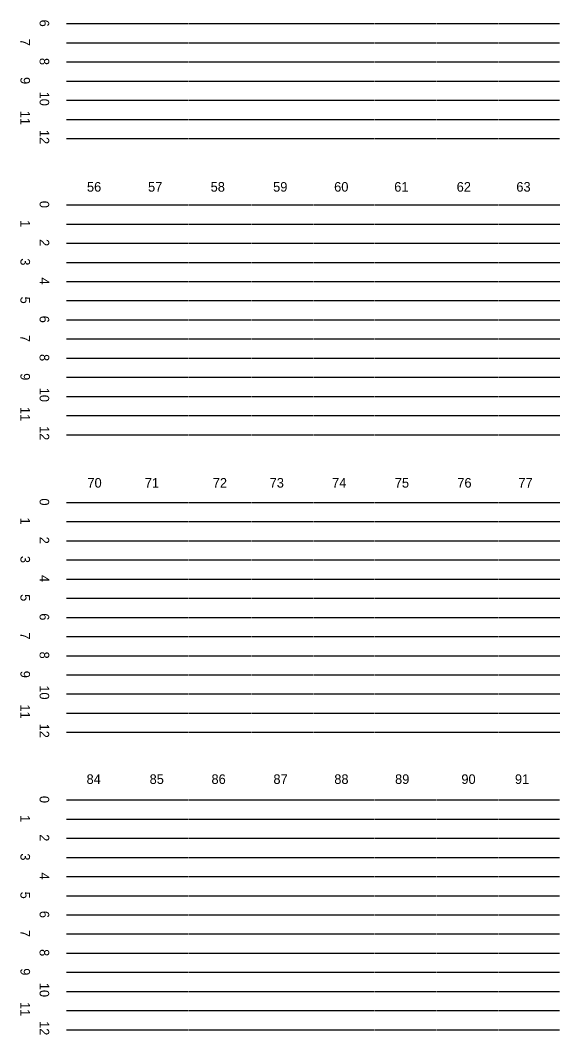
# Model space of a CAD drawing. Extents: x 11193 to 12507, y 10092 to 10555.
# Drawn here: x 11193.1 to 11315, y 10091.7 to 10321.2 of the extents above; entities that cross this region are included whole.
import ezdxf

# ---------------------------------------------------------------- set-up
doc = ezdxf.new("R2010")
doc.units = 0
doc.layers.add('Level 2', color=7, linetype='Continuous')

msp = doc.modelspace()

# ---------------------------------------------------------------- linework, layer by layer
at = {"layer": 'Level 2'}
for p, q in [((11203.54, 10320.47), (11217.46, 10320.47)), ((11217.56, 10320.47), (11231.14, 10320.47)), ((11231.24, 10320.47), (11245.22, 10320.47)), ((11245.32, 10320.47), (11259.3, 10320.47)), ((11259.41, 10320.47), (11273.18, 10320.47)), ((11273.29, 10320.47), (11287.06, 10320.47)), ((11287.17, 10320.47), (11301.14, 10320.47)), ((11301.25, 10320.47), (11315.03, 10320.47)), ((11203.54, 10316.14), (11217.46, 10316.14)), ((11217.56, 10316.14), (11231.14, 10316.14)), ((11231.24, 10316.14), (11245.22, 10316.14)), ((11245.32, 10316.14), (11259.3, 10316.14)), ((11259.41, 10316.14), (11273.18, 10316.14)), ((11273.29, 10316.14), (11287.06, 10316.14)), ((11287.17, 10316.14), (11301.14, 10316.14)), ((11301.25, 10316.14), (11315.03, 10316.14)), ((11203.54, 10311.81), (11217.46, 10311.81)), ((11217.56, 10311.81), (11231.14, 10311.81)), ((11231.24, 10311.81), (11245.22, 10311.81)), ((11245.32, 10311.81), (11259.3, 10311.81)), ((11259.41, 10311.81), (11273.18, 10311.81)), ((11273.29, 10311.81), (11287.06, 10311.81)), ((11287.17, 10311.81), (11301.14, 10311.81)), ((11301.25, 10311.81), (11315.03, 10311.81)), ((11203.54, 10307.48), (11217.46, 10307.48)), ((11217.56, 10307.48), (11231.14, 10307.48)), ((11231.24, 10307.48), (11245.22, 10307.48)), ((11245.32, 10307.48), (11259.3, 10307.48)), ((11259.41, 10307.48), (11273.18, 10307.48)), ((11273.29, 10307.48), (11287.06, 10307.48)), ((11287.17, 10307.48), (11301.14, 10307.48)), ((11301.25, 10307.48), (11315.03, 10307.48)), ((11203.54, 10303.14), (11217.46, 10303.14)), ((11217.56, 10303.14), (11231.14, 10303.14)), ((11231.24, 10303.14), (11245.22, 10303.14)), ((11245.32, 10303.14), (11259.3, 10303.14)), ((11259.41, 10303.14), (11273.18, 10303.14)), ((11273.29, 10303.14), (11287.06, 10303.14)), ((11287.17, 10303.14), (11301.14, 10303.14)), ((11301.25, 10303.14), (11315.03, 10303.14)), ((11203.54, 10298.81), (11217.46, 10298.81)), ((11217.56, 10298.81), (11231.14, 10298.81)), ((11231.24, 10298.81), (11245.22, 10298.81)), ((11245.32, 10298.81), (11259.3, 10298.81)), ((11259.41, 10298.81), (11273.18, 10298.81)), ((11273.29, 10298.81), (11287.06, 10298.81)), ((11287.17, 10298.81), (11301.14, 10298.81)), ((11301.25, 10298.81), (11315.03, 10298.81)), ((11203.54, 10294.48), (11217.46, 10294.48)), ((11217.56, 10294.48), (11231.14, 10294.48)), ((11231.24, 10294.48), (11245.22, 10294.48)), ((11245.32, 10294.48), (11259.3, 10294.48)), ((11259.41, 10294.48), (11273.18, 10294.48)), ((11273.29, 10294.48), (11287.06, 10294.48)), ((11287.17, 10294.48), (11301.14, 10294.48)), ((11301.25, 10294.48), (11315.03, 10294.48)), ((11203.54, 10279.46), (11217.47, 10279.46)), ((11217.59, 10279.46), (11231.15, 10279.46)), ((11231.26, 10279.46), (11245.23, 10279.46)), ((11245.35, 10279.46), (11259.31, 10279.46)), ((11259.43, 10279.46), (11273.2, 10279.46)), ((11273.31, 10279.46), (11287.08, 10279.46)), ((11287.18, 10279.46), (11301.16, 10279.46)), ((11301.26, 10279.46), (11315.04, 10279.46)), ((11203.54, 10275.13), (11217.47, 10275.13)), ((11217.59, 10275.13), (11231.15, 10275.13)), ((11231.26, 10275.13), (11245.23, 10275.13)), ((11245.35, 10275.13), (11259.31, 10275.13)), ((11259.43, 10275.13), (11273.2, 10275.13)), ((11273.31, 10275.13), (11287.08, 10275.13)), ((11287.18, 10275.13), (11301.16, 10275.13)), ((11301.26, 10275.13), (11315.04, 10275.13)), ((11203.54, 10270.79), (11217.47, 10270.79)), ((11217.59, 10270.79), (11231.15, 10270.79)), ((11231.26, 10270.79), (11245.23, 10270.79)), ((11245.35, 10270.79), (11259.31, 10270.79)), ((11259.43, 10270.79), (11273.2, 10270.79)), ((11273.31, 10270.79), (11287.08, 10270.79)), ((11287.18, 10270.79), (11301.16, 10270.79)), ((11301.26, 10270.79), (11315.04, 10270.79)), ((11203.54, 10266.46), (11217.47, 10266.46)), ((11217.59, 10266.46), (11231.15, 10266.46)), ((11231.26, 10266.46), (11245.23, 10266.46)), ((11245.35, 10266.46), (11259.31, 10266.46)), ((11259.43, 10266.46), (11273.2, 10266.46)), ((11273.31, 10266.46), (11287.08, 10266.46)), ((11287.18, 10266.46), (11301.16, 10266.46)), ((11301.26, 10266.46), (11315.04, 10266.46)), ((11203.54, 10262.13), (11217.47, 10262.13)), ((11217.59, 10262.13), (11231.15, 10262.13)), ((11231.26, 10262.13), (11245.23, 10262.13)), ((11245.35, 10262.13), (11259.31, 10262.13)), ((11259.43, 10262.13), (11273.2, 10262.13)), ((11273.31, 10262.13), (11287.08, 10262.13)), ((11287.18, 10262.13), (11301.16, 10262.13)), ((11301.26, 10262.13), (11315.04, 10262.13)), ((11203.54, 10257.8), (11217.47, 10257.8)), ((11217.59, 10257.8), (11231.15, 10257.8)), ((11231.26, 10257.8), (11245.23, 10257.8)), ((11245.35, 10257.8), (11259.31, 10257.8)), ((11259.43, 10257.8), (11273.2, 10257.8)), ((11273.31, 10257.8), (11287.08, 10257.8)), ((11287.18, 10257.8), (11301.16, 10257.8)), ((11301.26, 10257.8), (11315.04, 10257.8)), ((11203.54, 10253.47), (11217.47, 10253.47)), ((11217.59, 10253.47), (11231.15, 10253.47)), ((11231.26, 10253.47), (11245.23, 10253.47)), ((11245.35, 10253.47), (11259.31, 10253.47)), ((11259.43, 10253.47), (11273.2, 10253.47)), ((11273.31, 10253.47), (11287.08, 10253.47)), ((11287.18, 10253.47), (11301.16, 10253.47)), ((11301.26, 10253.47), (11315.04, 10253.47)), ((11203.54, 10249.13), (11217.47, 10249.13)), ((11217.59, 10249.13), (11231.15, 10249.13)), ((11231.26, 10249.13), (11245.23, 10249.13)), ((11245.35, 10249.13), (11259.31, 10249.13)), ((11259.43, 10249.13), (11273.2, 10249.13)), ((11273.31, 10249.13), (11287.08, 10249.13)), ((11287.18, 10249.13), (11301.16, 10249.13)), ((11301.26, 10249.13), (11315.04, 10249.13)), ((11203.54, 10244.8), (11217.47, 10244.8)), ((11217.59, 10244.8), (11231.15, 10244.8)), ((11231.26, 10244.8), (11245.23, 10244.8)), ((11245.35, 10244.8), (11259.31, 10244.8)), ((11259.43, 10244.8), (11273.2, 10244.8)), ((11273.31, 10244.8), (11287.08, 10244.8)), ((11287.18, 10244.8), (11301.16, 10244.8)), ((11301.26, 10244.8), (11315.04, 10244.8)), ((11203.54, 10240.47), (11217.47, 10240.47)), ((11217.59, 10240.47), (11231.15, 10240.47)), ((11231.26, 10240.47), (11245.23, 10240.47)), ((11245.35, 10240.47), (11259.31, 10240.47)), ((11259.43, 10240.47), (11273.2, 10240.47)), ((11273.31, 10240.47), (11287.08, 10240.47)), ((11287.18, 10240.47), (11301.16, 10240.47)), ((11301.26, 10240.47), (11315.04, 10240.47)), ((11203.54, 10236.14), (11217.47, 10236.14)), ((11217.59, 10236.14), (11231.15, 10236.14)), ((11231.26, 10236.14), (11245.23, 10236.14)), ((11245.35, 10236.14), (11259.31, 10236.14)), ((11259.43, 10236.14), (11273.2, 10236.14)), ((11273.31, 10236.14), (11287.08, 10236.14)), ((11287.18, 10236.14), (11301.16, 10236.14)), ((11301.26, 10236.14), (11315.04, 10236.14)), ((11203.54, 10231.81), (11217.47, 10231.81)), ((11217.59, 10231.81), (11231.15, 10231.81)), ((11231.26, 10231.81), (11245.23, 10231.81)), ((11245.35, 10231.81), (11259.31, 10231.81)), ((11259.43, 10231.81), (11273.2, 10231.81)), ((11273.31, 10231.81), (11287.08, 10231.81)), ((11287.18, 10231.81), (11301.16, 10231.81)), ((11301.26, 10231.81), (11315.04, 10231.81)), ((11203.54, 10227.47), (11217.47, 10227.47)), ((11217.59, 10227.47), (11231.15, 10227.47)), ((11231.26, 10227.47), (11245.23, 10227.47)), ((11245.35, 10227.47), (11259.31, 10227.47)), ((11259.43, 10227.47), (11273.2, 10227.47)), ((11273.31, 10227.47), (11287.08, 10227.47)), ((11287.18, 10227.47), (11301.16, 10227.47)), ((11301.26, 10227.47), (11315.04, 10227.47)), ((11203.54, 10212.14), (11217.47, 10212.14)), ((11217.59, 10212.14), (11231.15, 10212.14)), ((11231.26, 10212.14), (11245.23, 10212.14)), ((11245.35, 10212.14), (11259.31, 10212.14)), ((11259.43, 10212.14), (11273.2, 10212.14)), ((11273.31, 10212.14), (11287.08, 10212.14)), ((11287.18, 10212.14), (11301.16, 10212.14)), ((11301.26, 10212.14), (11315.04, 10212.14)), ((11203.54, 10207.81), (11217.47, 10207.81)), ((11217.59, 10207.81), (11231.15, 10207.81)), ((11231.26, 10207.81), (11245.23, 10207.81)), ((11245.35, 10207.81), (11259.31, 10207.81)), ((11259.43, 10207.81), (11273.2, 10207.81)), ((11273.31, 10207.81), (11287.08, 10207.81)), ((11287.18, 10207.81), (11301.16, 10207.81)), ((11301.26, 10207.81), (11315.04, 10207.81)), ((11203.54, 10203.48), (11217.47, 10203.48)), ((11217.59, 10203.48), (11231.15, 10203.48)), ((11231.26, 10203.48), (11245.23, 10203.48)), ((11245.35, 10203.48), (11259.31, 10203.48)), ((11259.43, 10203.48), (11273.2, 10203.48)), ((11273.31, 10203.48), (11287.08, 10203.48)), ((11287.18, 10203.48), (11301.16, 10203.48)), ((11301.26, 10203.48), (11315.04, 10203.48)), ((11203.54, 10199.14), (11217.47, 10199.14)), ((11217.59, 10199.14), (11231.15, 10199.14)), ((11231.26, 10199.14), (11245.23, 10199.14)), ((11245.35, 10199.14), (11259.31, 10199.14)), ((11259.43, 10199.14), (11273.2, 10199.14)), ((11273.31, 10199.14), (11287.08, 10199.14)), ((11287.18, 10199.14), (11301.16, 10199.14)), ((11301.26, 10199.14), (11315.04, 10199.14)), ((11203.54, 10194.81), (11217.47, 10194.81)), ((11217.59, 10194.81), (11231.15, 10194.81)), ((11231.26, 10194.81), (11245.23, 10194.81)), ((11245.35, 10194.81), (11259.31, 10194.81)), ((11259.43, 10194.81), (11273.2, 10194.81)), ((11273.31, 10194.81), (11287.08, 10194.81)), ((11287.18, 10194.81), (11301.16, 10194.81)), ((11301.26, 10194.81), (11315.04, 10194.81)), ((11203.54, 10190.48), (11217.47, 10190.48)), ((11217.59, 10190.48), (11231.15, 10190.48)), ((11231.26, 10190.48), (11245.23, 10190.48)), ((11245.35, 10190.48), (11259.31, 10190.48)), ((11259.43, 10190.48), (11273.2, 10190.48)), ((11273.31, 10190.48), (11287.08, 10190.48)), ((11287.18, 10190.48), (11301.16, 10190.48)), ((11301.26, 10190.48), (11315.04, 10190.48)), ((11203.54, 10186.15), (11217.47, 10186.15)), ((11217.59, 10186.15), (11231.15, 10186.15)), ((11231.26, 10186.15), (11245.23, 10186.15)), ((11245.35, 10186.15), (11259.31, 10186.15)), ((11259.43, 10186.15), (11273.2, 10186.15)), ((11273.31, 10186.15), (11287.08, 10186.15)), ((11287.18, 10186.15), (11301.16, 10186.15)), ((11301.26, 10186.15), (11315.04, 10186.15)), ((11203.54, 10181.82), (11217.47, 10181.82)), ((11217.59, 10181.82), (11231.15, 10181.82)), ((11231.26, 10181.82), (11245.23, 10181.82)), ((11245.35, 10181.82), (11259.31, 10181.82)), ((11259.43, 10181.82), (11273.2, 10181.82)), ((11273.31, 10181.82), (11287.08, 10181.82)), ((11287.18, 10181.82), (11301.16, 10181.82)), ((11301.26, 10181.82), (11315.04, 10181.82)), ((11203.54, 10177.48), (11217.47, 10177.48)), ((11217.59, 10177.48), (11231.15, 10177.48)), ((11231.26, 10177.48), (11245.23, 10177.48)), ((11245.35, 10177.48), (11259.31, 10177.48)), ((11259.43, 10177.48), (11273.2, 10177.48)), ((11273.31, 10177.48), (11287.08, 10177.48)), ((11287.18, 10177.48), (11301.16, 10177.48)), ((11301.26, 10177.48), (11315.04, 10177.48)), ((11203.54, 10173.15), (11217.47, 10173.15)), ((11217.59, 10173.15), (11231.15, 10173.15)), ((11231.26, 10173.15), (11245.23, 10173.15)), ((11245.35, 10173.15), (11259.31, 10173.15)), ((11259.43, 10173.15), (11273.2, 10173.15)), ((11273.31, 10173.15), (11287.08, 10173.15)), ((11287.18, 10173.15), (11301.16, 10173.15)), ((11301.26, 10173.15), (11315.04, 10173.15)), ((11203.54, 10168.82), (11217.47, 10168.82)), ((11217.59, 10168.82), (11231.15, 10168.82)), ((11231.26, 10168.82), (11245.23, 10168.82)), ((11245.35, 10168.82), (11259.31, 10168.82)), ((11259.43, 10168.82), (11273.2, 10168.82)), ((11273.31, 10168.82), (11287.08, 10168.82)), ((11287.18, 10168.82), (11301.16, 10168.82)), ((11301.26, 10168.82), (11315.04, 10168.82)), ((11203.54, 10164.49), (11217.47, 10164.49)), ((11217.59, 10164.49), (11231.15, 10164.49)), ((11231.26, 10164.49), (11245.23, 10164.49)), ((11245.35, 10164.49), (11259.31, 10164.49)), ((11259.43, 10164.49), (11273.2, 10164.49)), ((11273.31, 10164.49), (11287.08, 10164.49)), ((11287.18, 10164.49), (11301.16, 10164.49)), ((11301.26, 10164.49), (11315.04, 10164.49)), ((11203.54, 10160.16), (11217.47, 10160.16)), ((11217.59, 10160.16), (11231.15, 10160.16)), ((11231.26, 10160.16), (11245.23, 10160.16)), ((11245.35, 10160.16), (11259.31, 10160.16)), ((11259.43, 10160.16), (11273.2, 10160.16)), ((11273.31, 10160.16), (11287.08, 10160.16)), ((11287.18, 10160.16), (11301.16, 10160.16)), ((11301.26, 10160.16), (11315.04, 10160.16)), ((11203.54, 10144.83), (11217.46, 10144.83)), ((11217.56, 10144.83), (11231.14, 10144.83)), ((11231.24, 10144.83), (11245.22, 10144.83)), ((11245.32, 10144.83), (11259.3, 10144.83)), ((11259.41, 10144.83), (11273.18, 10144.83)), ((11273.29, 10144.83), (11287.06, 10144.83)), ((11287.17, 10144.83), (11301.14, 10144.83)), ((11301.25, 10144.83), (11315.03, 10144.83)), ((11203.54, 10140.5), (11217.46, 10140.5)), ((11217.56, 10140.5), (11231.14, 10140.5)), ((11231.24, 10140.5), (11245.22, 10140.5)), ((11245.32, 10140.5), (11259.3, 10140.5)), ((11259.41, 10140.5), (11273.18, 10140.5)), ((11273.29, 10140.5), (11287.06, 10140.5)), ((11287.17, 10140.5), (11301.14, 10140.5)), ((11301.25, 10140.5), (11315.03, 10140.5)), ((11203.54, 10136.17), (11217.46, 10136.17)), ((11217.56, 10136.17), (11231.14, 10136.17)), ((11231.24, 10136.17), (11245.22, 10136.17)), ((11245.32, 10136.17), (11259.3, 10136.17)), ((11259.41, 10136.17), (11273.18, 10136.17)), ((11273.29, 10136.17), (11287.06, 10136.17)), ((11287.17, 10136.17), (11301.14, 10136.17)), ((11301.25, 10136.17), (11315.03, 10136.17)), ((11203.54, 10131.84), (11217.46, 10131.84)), ((11217.56, 10131.84), (11231.14, 10131.84)), ((11231.24, 10131.84), (11245.22, 10131.84)), ((11245.32, 10131.84), (11259.3, 10131.84)), ((11259.41, 10131.84), (11273.18, 10131.84)), ((11273.29, 10131.84), (11287.06, 10131.84)), ((11287.17, 10131.84), (11301.14, 10131.84)), ((11301.25, 10131.84), (11315.03, 10131.84)), ((11203.54, 10127.51), (11217.46, 10127.51)), ((11217.56, 10127.51), (11231.14, 10127.51)), ((11231.24, 10127.51), (11245.22, 10127.51)), ((11245.32, 10127.51), (11259.3, 10127.51)), ((11259.41, 10127.51), (11273.18, 10127.51)), ((11273.29, 10127.51), (11287.06, 10127.51)), ((11287.17, 10127.51), (11301.14, 10127.51)), ((11301.25, 10127.51), (11315.03, 10127.51)), ((11203.54, 10123.17), (11217.46, 10123.17)), ((11217.56, 10123.17), (11231.14, 10123.17)), ((11231.24, 10123.17), (11245.22, 10123.17)), ((11245.32, 10123.17), (11259.3, 10123.17)), ((11259.41, 10123.17), (11273.18, 10123.17)), ((11273.29, 10123.17), (11287.06, 10123.17)), ((11287.17, 10123.17), (11301.14, 10123.17)), ((11301.25, 10123.17), (11315.03, 10123.17)), ((11203.54, 10118.84), (11217.46, 10118.84)), ((11217.56, 10118.84), (11231.14, 10118.84)), ((11231.24, 10118.84), (11245.22, 10118.84)), ((11245.32, 10118.84), (11259.3, 10118.84)), ((11259.41, 10118.84), (11273.18, 10118.84)), ((11273.29, 10118.84), (11287.06, 10118.84)), ((11287.17, 10118.84), (11301.14, 10118.84)), ((11301.25, 10118.84), (11315.03, 10118.84)), ((11203.54, 10114.51), (11217.46, 10114.51)), ((11217.56, 10114.51), (11231.14, 10114.51)), ((11231.24, 10114.51), (11245.22, 10114.51)), ((11245.32, 10114.51), (11259.3, 10114.51)), ((11259.41, 10114.51), (11273.18, 10114.51)), ((11273.29, 10114.51), (11287.06, 10114.51)), ((11287.17, 10114.51), (11301.14, 10114.51)), ((11301.25, 10114.51), (11315.03, 10114.51)), ((11203.54, 10110.18), (11217.46, 10110.18)), ((11217.56, 10110.18), (11231.14, 10110.18)), ((11231.24, 10110.18), (11245.22, 10110.18)), ((11245.32, 10110.18), (11259.3, 10110.18)), ((11259.41, 10110.18), (11273.18, 10110.18)), ((11273.29, 10110.18), (11287.06, 10110.18)), ((11287.17, 10110.18), (11301.14, 10110.18)), ((11301.25, 10110.18), (11315.03, 10110.18)), ((11203.54, 10105.85), (11217.46, 10105.85)), ((11217.56, 10105.85), (11231.14, 10105.85)), ((11231.24, 10105.85), (11245.22, 10105.85)), ((11245.32, 10105.85), (11259.3, 10105.85)), ((11259.41, 10105.85), (11273.18, 10105.85)), ((11273.29, 10105.85), (11287.06, 10105.85)), ((11287.17, 10105.85), (11301.14, 10105.85)), ((11301.25, 10105.85), (11315.03, 10105.85)), ((11203.54, 10101.51), (11217.46, 10101.51)), ((11217.56, 10101.51), (11231.14, 10101.51)), ((11231.24, 10101.51), (11245.22, 10101.51)), ((11245.32, 10101.51), (11259.3, 10101.51)), ((11259.41, 10101.51), (11273.18, 10101.51)), ((11273.29, 10101.51), (11287.06, 10101.51)), ((11287.17, 10101.51), (11301.14, 10101.51)), ((11301.25, 10101.51), (11315.03, 10101.51)), ((11203.54, 10097.18), (11217.46, 10097.18)), ((11217.56, 10097.18), (11231.14, 10097.18)), ((11231.24, 10097.18), (11245.22, 10097.18)), ((11245.32, 10097.18), (11259.3, 10097.18)), ((11259.41, 10097.18), (11273.18, 10097.18)), ((11273.29, 10097.18), (11287.06, 10097.18)), ((11287.17, 10097.18), (11301.14, 10097.18)), ((11301.25, 10097.18), (11315.03, 10097.18)), ((11203.54, 10092.85), (11217.46, 10092.85)), ((11217.56, 10092.85), (11231.14, 10092.85)), ((11231.24, 10092.85), (11245.22, 10092.85)), ((11245.32, 10092.85), (11259.3, 10092.85)), ((11259.41, 10092.85), (11273.18, 10092.85)), ((11273.29, 10092.85), (11287.06, 10092.85)), ((11287.17, 10092.85), (11301.14, 10092.85)), ((11301.25, 10092.85), (11315.03, 10092.85))]:
    msp.add_line(p, q, dxfattribs=at)

# ---------------------------------------------------------------- texts
for s, height, p in [('6', 2.17, (11197.46, 10321.38)), ('7', 2.17, (11193.13, 10317.05)), ('8', 2.17, (11197.46, 10312.72)), ('9', 2.17, (11193.13, 10308.39)), ('10', 2.166, (11197.46, 10305.09)), ('11', 2.166, (11193.13, 10300.76)), ('12', 2.166, (11197.46, 10296.43)), ('0', 2.17, (11197.46, 10280.38)), ('1', 2.17, (11193.13, 10276.05)), ('2', 2.17, (11197.46, 10271.72)), ('3', 2.17, (11193.13, 10267.38)), ('4', 2.17, (11197.46, 10263.05)), ('5', 2.17, (11193.13, 10258.72)), ('6', 2.17, (11197.46, 10254.39)), ('7', 2.17, (11193.13, 10250.06)), ('8', 2.17, (11197.46, 10245.72)), ('9', 2.17, (11193.13, 10241.39)), ('10', 2.166, (11197.46, 10238.1)), ('11', 2.166, (11193.13, 10233.76)), ('12', 2.166, (11197.46, 10229.43)), ('0', 2.17, (11197.46, 10213.06)), ('1', 2.17, (11193.13, 10208.73)), ('2', 2.17, (11197.46, 10204.4)), ('3', 2.17, (11193.13, 10200.06)), ('4', 2.17, (11197.46, 10195.73)), ('5', 2.17, (11193.13, 10191.4)), ('6', 2.17, (11197.46, 10187.07)), ('7', 2.17, (11193.13, 10182.74)), ('8', 2.17, (11197.46, 10178.4)), ('9', 2.17, (11193.13, 10174.07)), ('10', 2.166, (11197.46, 10170.78)), ('11', 2.166, (11193.13, 10166.44)), ('12', 2.166, (11197.46, 10162.11)), ('0', 2.17, (11197.46, 10145.75)), ('1', 2.17, (11193.13, 10141.41)), ('2', 2.17, (11197.46, 10137.08)), ('3', 2.17, (11193.13, 10132.75)), ('4', 2.17, (11197.46, 10128.42)), ('5', 2.17, (11193.13, 10124.09)), ('6', 2.17, (11197.46, 10119.75)), ('7', 2.17, (11193.13, 10115.42)), ('8', 2.17, (11197.46, 10111.09)), ('9', 2.17, (11193.13, 10106.76)), ('10', 2.166, (11197.46, 10103.46)), ('11', 2.166, (11193.13, 10099.13)), ('12', 2.166, (11197.46, 10094.8))]:
    msp.add_text(s, height=height, rotation=270, dxfattribs=at).set_placement(p)
for s, p in [('56', (11208.17, 10282.46)), ('57', (11221.98, 10282.46)), ('58', (11236.13, 10282.46)), ('59', (11250.25, 10282.46)), ('60', (11264.05, 10282.46)), ('61', (11277.64, 10282.46)), ('62', (11291.75, 10282.46)), ('63', (11305.24, 10282.46)), ('70', (11208.27, 10215.5)), ('71', (11221.24, 10215.5)), ('72', (11236.61, 10215.5)), ('73', (11249.47, 10215.5)), ('74', (11263.58, 10215.5)), ('75', (11277.76, 10215.5)), ('76', (11291.89, 10215.5)), ('77', (11305.7, 10215.5)), ('84', (11208.08, 10148.46)), ('85', (11222.33, 10148.46)), ('86', (11236.32, 10148.46)), ('87', (11250.32, 10148.46)), ('88', (11264.08, 10148.46)), ('89', (11277.82, 10148.46)), ('90', (11292.81, 10148.46)), ('91', (11304.92, 10148.46))]:
    msp.add_text(s, height=2.17, dxfattribs=at).set_placement(p)

doc.saveas('drawing.dxf')
